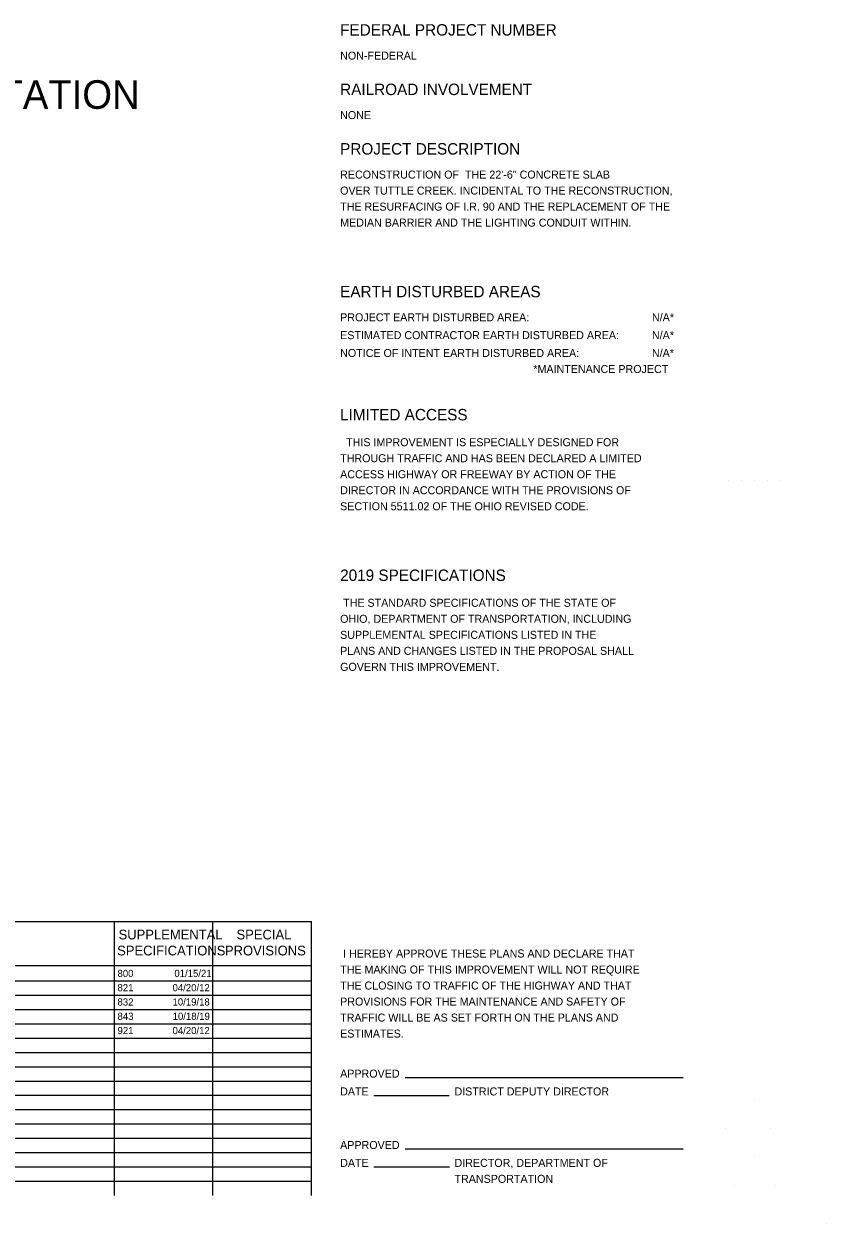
# Model space of a CAD drawing. Extents: x 2080852 to 2433556, y 1080825 to 1306626.
# Drawn here: x 2285387 to 2433556, y 1080825 to 1302410 of the extents above; entities that cross this region are included whole.
import ezdxf

# ---------------------------------------------------------------- set-up
doc = ezdxf.new("R2010")
doc.units = 0
for name, color, linetype in [('Default', 7, 'Continuous'), ('PM_P_Lane_Line', 7, 'Continuous'), ('SC_Scratch1', 7, 'Continuous')]:
    doc.layers.add(name, color=color, linetype=linetype)

msp = doc.modelspace()

# ---------------------------------------------------------------- linework, layer by layer
at = {"layer": 'PM_P_Lane_Line'}
for p, q in [((2196484, 1136706), (2338516, 1136706)), ((2302084, 1086105), (2302084, 1136706)), ((2320300, 1086105), (2320300, 1136706)), ((2338516, 1086105), (2338516, 1136706)), ((2196484, 1128566), (2338516, 1128566)), ((2196484, 1125705), (2338516, 1125705)), ((2196484, 1123065), (2338516, 1123065)), ((2196484, 1120425), (2338516, 1120425)), ((2196484, 1117785), (2338516, 1117785)), ((2196484, 1115145), (2338516, 1115145)), ((2196484, 1112505), (2338516, 1112505)), ((2196484, 1109865), (2338516, 1109865)), ((2196484, 1107225), (2338516, 1107225)), ((2355780, 1107857), (2407156, 1107857)), ((2196484, 1104585), (2338516, 1104585)), ((2350032, 1104562), (2363947, 1104562)), ((2196484, 1101945), (2338516, 1101945)), ((2196484, 1099305), (2338516, 1099305)), ((2196484, 1096665), (2338516, 1096665)), ((2355780, 1094675), (2407156, 1094675)), ((2196484, 1094025), (2338516, 1094025)), ((2196484, 1091385), (2338516, 1091385)), ((2350032, 1091379), (2364007, 1091379)), ((2196484, 1088745), (2338516, 1088745))]:
    msp.add_line(p, q, dxfattribs=at)
at = {"layer": 'SC_Scratch1'}
for p, q in [((2415604, 1218105), (2415604, 1218105)), ((2417980, 1218105), (2417980, 1218105)), ((2420356, 1218105), (2420356, 1218105)), ((2422732, 1218105), (2422732, 1218105)), ((2425108, 1218105), (2425108, 1218105)), ((2420356, 1103793), (2420356, 1103793)), ((2415076, 1098513), (2415076, 1098513)), ((2423260, 1098513), (2423260, 1098513)), ((2420356, 1093233), (2420356, 1093233)), ((2416396, 1087953), (2416396, 1087953)), ((2424316, 1087953), (2424316, 1087953)), ((2433556, 1080825), (2433556, 1080825))]:
    msp.add_line(p, q, dxfattribs=at)

# ---------------------------------------------------------------- texts
at = {"layer": 'Default'}
for s, height, p in [('FEDERAL PROJECT NUMBER', 2112, (2343796, 1300267)), ('NON-FEDERAL', 1478.4, (2343796, 1295832)), ('DEPARTMENT OF TRANSPORTATION', 5280, (2179267, 1286745)), ('RAILROAD INVOLVEMENT', 2112, (2343796, 1289284)), ('NONE', 1478.4, (2343796, 1284849)), ('DISTRICT DEPUTY DIRECTOR', 1478.4, (2364916, 1104562)), ('DIRECTOR, DEPARTMENT OF', 1478.4, (2364916, 1091377)), ('TRANSPORTATION', 1478.4, (2364916, 1088420))]:
    msp.add_text(s, height=height, dxfattribs=at).set_placement(p)
at = {"layer": 'PM_P_Lane_Line'}
for s, height, p in [('PROJECT DESCRIPTION', 2112, (2343796, 1278302)), ('RECONSTRUCTION OF  THE 22\'-6" CONCRETE SLAB', 1478.4, (2343796, 1273867)), ('OVER TUTTLE CREEK. INCIDENTAL TO THE RECONSTRUCTION,', 1478.4, (2343796, 1270910)), ('THE RESURFACING OF I.R. 90 AND THE REPLACEMENT OF THE', 1478.4, (2343796, 1267953)), ('MEDIAN BARRIER AND THE LIGHTING CONDUIT WITHIN.', 1478.4, (2343796, 1264996)), ('EARTH DISTURBED AREAS', 2112, (2343796, 1251944)), ('PROJECT EARTH DISTURBED AREA:', 1478.4, (2343796, 1247509)), ('N/A*', 1478.4, (2401402, 1247509)), ('ESTIMATED CONTRACTOR EARTH DISTURBED AREA:', 1478.4, (2343796, 1244214)), ('N/A*', 1478.4, (2401401, 1244214)), ('NOTICE OF INTENT EARTH DISTURBED AREA:', 1478.4, (2343796, 1240920)), ('N/A*', 1478.4, (2401401, 1240920)), ('*MAINTENANCE PROJECT', 1478.4, (2379490, 1237963)), ('LIMITED ACCESS', 2112, (2343796, 1229219)), ('  THIS IMPROVEMENT IS ESPECIALLY DESIGNED FOR', 1478.4, (2343796, 1224446)), ('THROUGH TRAFFIC AND HAS BEEN DECLARED A LIMITED', 1478.4, (2343796, 1221489)), ('ACCESS HIGHWAY OR FREEWAY BY ACTION OF THE', 1478.4, (2343796, 1218532)), ('DIRECTOR IN ACCORDANCE WITH THE PROVISIONS OF', 1478.4, (2343796, 1215576)), ('SECTION 5511.02 OF THE OHIO REVISED CODE.', 1478.4, (2343796, 1212619)), ('2019 SPECIFICATIONS', 2112, (2343796, 1199567)), (' THE STANDARD SPECIFICATIONS OF THE STATE OF', 1478.4, (2343796, 1194793)), ('OHIO, DEPARTMENT OF TRANSPORTATION, INCLUDING', 1478.4, (2343796, 1191837)), ('SUPPLEMENTAL SPECIFICATIONS LISTED IN THE', 1478.4, (2343796, 1188880)), ('PLANS AND CHANGES LISTED IN THE PROPOSAL SHALL', 1478.4, (2343796, 1185923)), ('GOVERN THIS IMPROVEMENT.', 1478.4, (2343796, 1182966)), ('SUPPLEMENTAL', 1795.2, (2302863, 1133375)), ('SPECIAL', 1795.2, (2324644, 1133375)), ('SPECIFICATIONS', 1795.2, (2302593, 1130418)), ('PROVISIONS', 1795.2, (2322510, 1130418)), (' I HEREBY APPROVE THESE PLANS AND DECLARE THAT', 1478.4, (2343796, 1130033)), ('THE MAKING OF THIS IMPROVEMENT WILL NOT REQUIRE', 1478.4, (2343796, 1127076)), ('800', 1320, (2302665, 1126444)), ('01/15/21', 1320, (2313176, 1126444)), ('821', 1320, (2302665, 1123804)), ('04/20/12', 1320, (2312836, 1123804)), ('THE CLOSING TO TRAFFIC OF THE HIGHWAY AND THAT', 1478.4, (2343796, 1124119)), ('832', 1320, (2302665, 1121164)), ('10/19/18', 1320, (2312832, 1121164)), ('PROVISIONS FOR THE MAINTENANCE AND SAFETY OF', 1478.4, (2343796, 1121162)), ('843', 1320, (2302665, 1118524)), ('10/18/19', 1320, (2312854, 1118524)), ('TRAFFIC WILL BE AS SET FORTH ON THE PLANS AND', 1478.4, (2343796, 1118205)), ('921', 1320, (2302665, 1115884)), ('04/20/12', 1320, (2312836, 1115884)), ('ESTIMATES.', 1478.4, (2343796, 1115249)), ('APPROVED', 1478.4, (2343796, 1107857)), ('DATE', 1478.4, (2343796, 1104562)), ('APPROVED', 1478.4, (2343796, 1094675)), ('DATE', 1478.4, (2343796, 1091379))]:
    msp.add_text(s, height=height, dxfattribs=at).set_placement(p)

doc.saveas('drawing.dxf')
